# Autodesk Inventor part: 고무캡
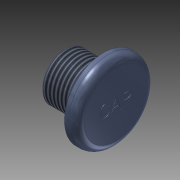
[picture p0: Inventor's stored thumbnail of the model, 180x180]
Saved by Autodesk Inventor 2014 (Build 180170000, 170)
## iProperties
Created: 2017-06
Part Number: 고무캡
Material: 고무
Document SubType Name: Modeling
Designer: mduedu
Density: 1 g/cm^3
Appearance: 고무 - 파란색 - 버전 1.1
Author: mduedu
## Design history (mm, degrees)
sketch "스케치1"
  geometry: L1 (0, 0)-(13, 0); L2 (13, 0)-(13, 10); L3 (13, 10)-(10, 10); L4 (0, 6)-(0, 0); L5 (0, 6)-(8, 6); L6 (8, 6)-(8, 8); L7 (8, 8)-(10, 8); L8 (10, 8)-(10, 10)
  constraints: 16 end point, 2 horizontal, 2 parallel, 2 perpendicular, 2 point on line, 1 vertical
  dimensions: "d0" = 20 diameter of L3 L1; "d2" = 12 diameter of L5 L1; "d6" = 5 distance between parallel lines of L2 L6; "d8" = 16 diameter of L7 L1; "d9" = 8 distance between parallel lines of L6 L4; "d32" = 2 distance of L6.end L7.end
revolve "회전1" sketch "스케치1" stored, may be unused: angle "d10" = 90 deg
hole "구멍1" diameter "d22" = 5; stored, may be unused: countersink angle "d26" = 90 deg, drill point angle "d28" = 0 deg; dims "d23" = 6, "d24" = 4, "d25" = 2, "d27" = 6, "d30" = 10, "d31" = 10
chamfer "모따기1" distance "d13" = 0.5; stored, may be unused: second distance "d14" = 2, angle "d15" = 45 deg
fillet "모깎기3" dims "d29" = 1
fillet "모깎기2" dims "d17" = 2
sketch "스케치3"
  geometry: 2 further points
  constraints: 1 coincident, 1 other
feature "엠보싱1" sketch "스케치3" dims "d18" = 0.2, "d19" = 0, "d29" = 1
feature "스레드1" dims "d33" = 10, "d34" = 0
node "솔리드1"
